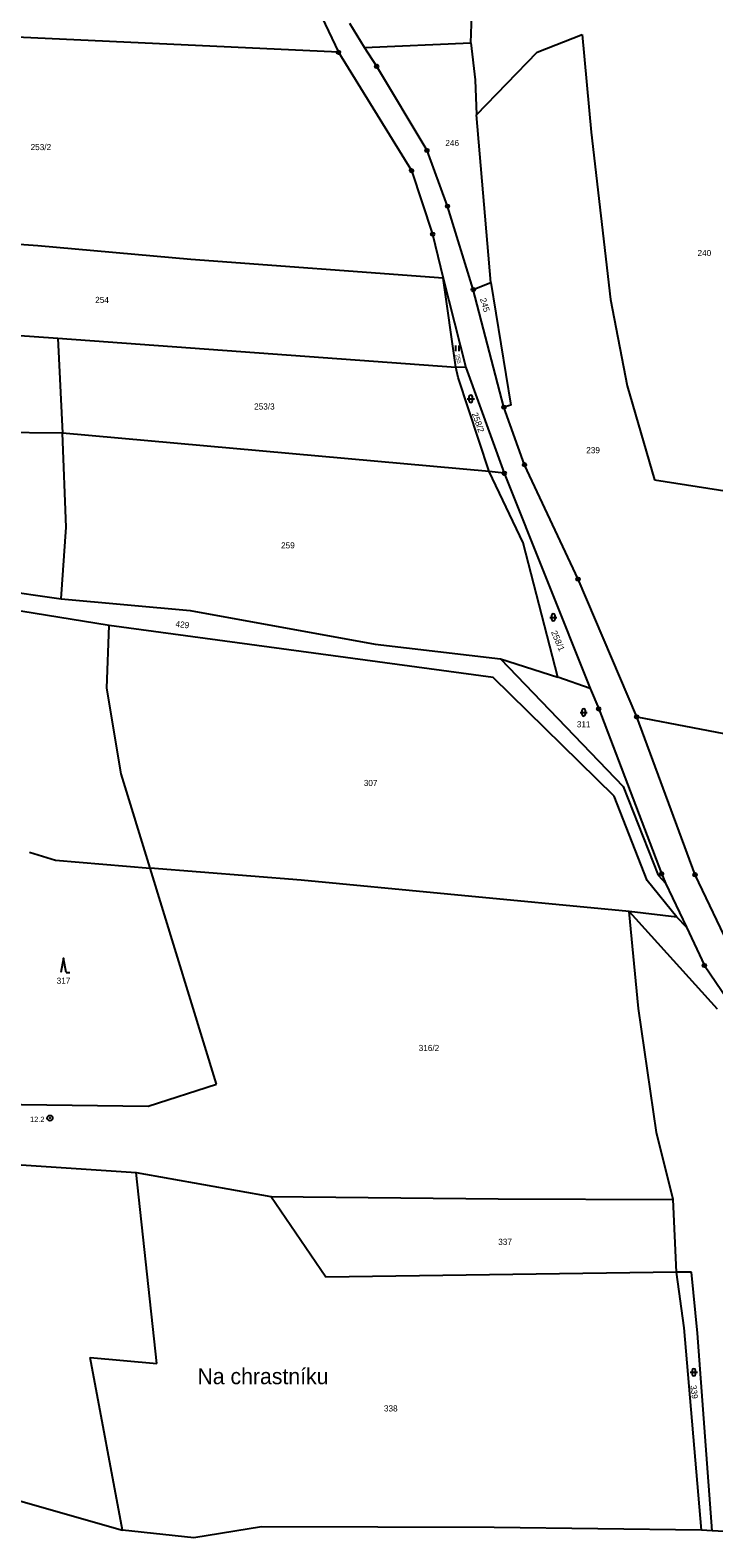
# Model space of a CAD drawing. Extents: x -791548 to -789311, y -1142631 to -1140855.
# Drawn here: x -790850.9 to -790661.5, y -1141946.5 to -1141528.8 of the extents above; entities that cross this region are included whole.
import ezdxf
from ezdxf.enums import TextEntityAlignment as Align

# ---------------------------------------------------------------- set-up
doc = ezdxf.new("R2010")
doc.units = 0
doc.header["$LTSCALE"] = 0.68
for name, color, linetype, lineweight in [('1', 7, 'Continuous', 25), ('3', 7, 'Continuous', 25), ('7', 7, 'Continuous', 13), ('8', 7, 'Continuous', 25)]:
    doc.layers.add(name, color=color, linetype=linetype, lineweight=lineweight)
doc.layers.add('2', color=7, linetype='Continuous')

msp = doc.modelspace()

# ---------------------------------------------------------------- linework, layer by layer
at = {"layer": '1'}
for p, q in [((-790728.86, -1141532.28), (-790728.17, -1141512.41)), ((-790773.86, -1141517.27), (-790765.51, -1141534.95)), ((-790765.51, -1141534.95), (-790858.67, -1141530.56)), ((-790758.27, -1141533.6), (-790762.39, -1141526.97)), ((-790710.48, -1141534.93), (-790698.03, -1141530)), ((-790698.03, -1141530), (-790695.46, -1141557.09)), ((-790758.27, -1141533.6), (-790728.86, -1141532.28)), ((-790754.91, -1141538.86), (-790758.27, -1141533.6)), ((-790728.86, -1141532.28), (-790727.65, -1141542.57)), ((-790765.51, -1141534.95), (-790745.26, -1141567.74)), ((-790740.97, -1141562.16), (-790754.91, -1141538.86)), ((-790727.28, -1141552.3), (-790710.48, -1141534.93)), ((-790727.65, -1141542.57), (-790727.28, -1141552.3)), ((-790723.3, -1141598.76), (-790727.28, -1141552.3)), ((-790695.46, -1141557.09), (-790690.18, -1141603.43)), ((-790735.29, -1141577.58), (-790740.97, -1141562.16)), ((-790745.26, -1141567.74), (-790739.41, -1141585.34)), ((-790728.17, -1141600.68), (-790735.29, -1141577.58)), ((-790848.8, -1141588.58), (-790927.3, -1141582.95)), ((-790806.37, -1141592.33), (-790848.8, -1141588.58)), ((-790739.41, -1141585.34), (-790736.47, -1141597.56)), ((-790736.47, -1141597.56), (-790806.37, -1141592.33)), ((-790732.95, -1141622.2), (-790736.47, -1141597.56)), ((-790736.47, -1141597.56), (-790730.25, -1141622.31)), ((-790728.17, -1141600.68), (-790723.3, -1141598.76)), ((-790719.68, -1141633.27), (-790728.17, -1141600.68)), ((-790723.3, -1141598.76), (-790717.78, -1141632.68)), ((-790690.18, -1141603.43), (-790685.56, -1141627.37)), ((-790918.49, -1141609.09), (-790843.22, -1141614.13)), ((-790843.22, -1141614.13), (-790841.97, -1141640.5)), ((-790843.22, -1141614.13), (-790732.95, -1141622.2)), ((-790732.38, -1141625.05), (-790732.95, -1141622.2)), ((-790730.25, -1141622.31), (-790732.95, -1141622.2)), ((-790730.25, -1141622.31), (-790719.56, -1141651.58)), ((-790723.76, -1141651.14), (-790732.38, -1141625.05)), ((-790685.56, -1141627.37), (-790678, -1141653.37)), ((-790717.78, -1141632.68), (-790719.68, -1141633.27)), ((-790713.97, -1141649.21), (-790719.68, -1141633.27)), ((-790841.97, -1141640.5), (-790867.82, -1141640.21)), ((-790723.76, -1141651.14), (-790841.97, -1141640.5)), ((-790840.96, -1141666.49), (-790841.97, -1141640.5)), ((-790719.56, -1141651.58), (-790723.76, -1141651.14)), ((-790714.34, -1141670.86), (-790723.76, -1141651.14)), ((-790719.56, -1141651.58), (-790695.74, -1141711.19)), ((-790699.13, -1141680.92), (-790713.97, -1141649.21)), ((-790678, -1141653.37), (-790657.29, -1141656.65)), ((-790842.32, -1141686.33), (-790840.96, -1141666.49)), ((-790704.7, -1141708.12), (-790714.34, -1141670.86)), ((-790682.89, -1141719.09), (-790699.13, -1141680.92)), ((-790876.48, -1141681.58), (-790842.32, -1141686.33)), ((-790829.04, -1141693.74), (-790876, -1141686.18)), ((-790842.32, -1141686.33), (-790806.62, -1141689.56)), ((-790806.62, -1141689.56), (-790755.32, -1141698.9)), ((-790829.64, -1141711.14), (-790829.04, -1141693.74)), ((-790722.67, -1141708.15), (-790829.04, -1141693.74)), ((-790755.32, -1141698.9), (-790720.64, -1141702.99)), ((-790720.64, -1141702.99), (-790704.7, -1141708.12)), ((-790720.64, -1141702.99), (-790686.64, -1141738.35)), ((-790689.14, -1141741.02), (-790722.67, -1141708.15)), ((-790695.74, -1141711.19), (-790704.7, -1141708.12)), ((-790825.67, -1141734.82), (-790829.64, -1141711.14)), ((-790695.74, -1141711.19), (-790693.42, -1141716.86)), ((-790693.42, -1141716.86), (-790675.99, -1141762.51)), ((-790666.72, -1141762.82), (-790682.89, -1141719.09)), ((-790682.89, -1141719.09), (-790633.79, -1141728.5)), ((-790817.67, -1141760.96), (-790825.67, -1141734.82)), ((-790686.64, -1141738.35), (-790676.99, -1141762.89)), ((-790679.96, -1141764.42), (-790689.14, -1141741.02)), ((-790851.12, -1141756.58), (-790843.88, -1141758.74)), ((-790843.88, -1141758.74), (-790817.67, -1141760.96)), ((-790775.82, -1141764.34), (-790817.67, -1141760.96)), ((-790799.25, -1141820.82), (-790817.67, -1141760.96)), ((-790735.29, -1141768.23), (-790775.82, -1141764.34)), ((-790671.78, -1141774.56), (-790679.96, -1141764.42)), ((-790676.99, -1141762.89), (-790674.87, -1141765.19)), ((-790675.99, -1141762.51), (-790674.87, -1141765.19)), ((-790656.61, -1141783.86), (-790666.72, -1141762.82)), ((-790684.96, -1141773), (-790735.29, -1141768.23)), ((-790674.87, -1141765.19), (-790669.06, -1141777.3)), ((-790684.96, -1141773), (-790660.62, -1141799.97)), ((-790682.37, -1141799.92), (-790684.96, -1141773)), ((-790671.78, -1141774.56), (-790684.96, -1141773)), ((-790669.06, -1141777.3), (-790671.78, -1141774.56)), ((-790669.06, -1141777.3), (-790664.13, -1141787.97)), ((-790664.13, -1141787.97), (-790656.26, -1141799.55)), ((-790677.43, -1141834.27), (-790682.37, -1141799.92)), ((-790818.25, -1141826.98), (-790799.25, -1141820.82)), ((-790867.97, -1141826.29), (-790818.25, -1141826.98)), ((-790672.75, -1141852.8), (-790677.43, -1141834.27)), ((-790920.31, -1141838.67), (-790821.51, -1141845.34)), ((-790821.51, -1141845.34), (-790784.23, -1141851.93)), ((-790815.8, -1141898.26), (-790821.51, -1141845.34)), ((-790769.02, -1141874.28), (-790784.23, -1141851.93)), ((-790784.23, -1141851.93), (-790721.23, -1141852.63)), ((-790721.23, -1141852.63), (-790672.75, -1141852.8)), ((-790671.88, -1141872.96), (-790672.75, -1141852.8)), ((-790671.88, -1141872.96), (-790769.02, -1141874.28)), ((-790667.69, -1141872.9), (-790671.88, -1141872.96)), ((-790669.75, -1141888.37), (-790671.88, -1141872.96)), ((-790666.08, -1141889.8), (-790667.69, -1141872.9)), ((-790664.9, -1141944.39), (-790669.75, -1141888.37)), ((-790662.02, -1141944.57), (-790666.08, -1141889.8)), ((-790825.32, -1141944.44), (-790834.23, -1141896.56)), ((-790834.23, -1141896.56), (-790815.8, -1141898.26)), ((-790853.52, -1141936.36), (-790825.32, -1141944.44)), ((-790786.82, -1141943.46), (-790805.54, -1141946.54)), ((-790722.41, -1141943.69), (-790786.82, -1141943.46)), ((-790664.9, -1141944.39), (-790722.41, -1141943.69)), ((-790805.54, -1141946.54), (-790825.32, -1141944.44)), ((-790662.02, -1141944.57), (-790664.9, -1141944.39)), ((-790650.61, -1141945.25), (-790662.02, -1141944.57))]:
    msp.add_line(p, q, dxfattribs=at)
at = {"layer": '3'}
for p, q in [((-790733.021, -1141617.72), (-790733.021, -1141616.22)), ((-790732.02, -1141617.72), (-790732.02, -1141616.22)), ((-790729.861, -1141630.951), (-790727.859, -1141630.951)), ((-790729.361, -1141630.451), (-790729.361, -1141631.452)), ((-790728.359, -1141631.452), (-790728.359, -1141630.451)), ((-790706.991, -1141691.511), (-790704.989, -1141691.511)), ((-790706.491, -1141691.011), (-790706.491, -1141692.012)), ((-790705.489, -1141692.012), (-790705.489, -1141691.011)), ((-790698.581, -1141717.841), (-790696.579, -1141717.841)), ((-790698.081, -1141717.341), (-790698.081, -1141718.342)), ((-790697.079, -1141718.342), (-790697.079, -1141717.341)), ((-790840.91, -1141789.9), (-790839.914, -1141789.9)), ((-790668.061, -1141900.671), (-790666.059, -1141900.671)), ((-790667.561, -1141900.171), (-790667.561, -1141901.172)), ((-790666.559, -1141901.172), (-790666.559, -1141900.171))]:
    msp.add_line(p, q, dxfattribs=at)
msp.add_lwpolyline([(-790840.91, -1141789.9), (-790841.66, -1141785.9), (-790842.41, -1141789.9)], dxfattribs=at)
for centre, start, end in [((-790728.86, -1141630.4509), 0, 180), ((-790728.86, -1141631.4509), 180, 359.98789), ((-790705.99, -1141691.0109), 0, 180), ((-790705.99, -1141692.0109), 180, 359.98789), ((-790697.58, -1141717.3409), 0, 180), ((-790697.58, -1141718.3409), 180, 359.98789), ((-790667.06, -1141900.1709), 0, 180), ((-790667.06, -1141901.1709), 180, 359.98789)]:
    msp.add_arc(centre, 0.5, start, end, dxfattribs=at)
at = {"layer": '8'}
for centre, radius in [((-790765.5099, -1141534.95), 0.5), ((-790765.5099, -1141534.95), 0.0303), ((-790754.9099, -1141538.86), 0.5), ((-790754.9099, -1141538.86), 0.0303), ((-790740.9699, -1141562.16), 0.5), ((-790740.9699, -1141562.16), 0.0303), ((-790745.2599, -1141567.74), 0.5), ((-790745.2599, -1141567.74), 0.0303), ((-790735.2899, -1141577.58), 0.5), ((-790735.2899, -1141577.58), 0.0303), ((-790739.4099, -1141585.34), 0.5), ((-790739.4099, -1141585.34), 0.0303), ((-790728.1699, -1141600.68), 0.5), ((-790728.1699, -1141600.68), 0.0303), ((-790719.6799, -1141633.27), 0.5), ((-790719.6799, -1141633.27), 0.0303), ((-790719.5599, -1141651.58), 0.5), ((-790719.5599, -1141651.58), 0.0303), ((-790713.9699, -1141649.21), 0.5), ((-790713.9699, -1141649.21), 0.0303), ((-790699.1299, -1141680.92), 0.5), ((-790699.1299, -1141680.92), 0.0303), ((-790693.4199, -1141716.86), 0.5), ((-790693.4199, -1141716.86), 0.0303), ((-790682.8899, -1141719.09), 0.5), ((-790682.8899, -1141719.09), 0.0303), ((-790675.9899, -1141762.51), 0.5), ((-790675.9899, -1141762.51), 0.0303), ((-790666.7199, -1141762.82), 0.5), ((-790666.7199, -1141762.82), 0.0303), ((-790664.1299, -1141787.97), 0.5), ((-790664.1299, -1141787.97), 0.0303), ((-790845.42, -1141830.2298), 0.75), ((-790845.42, -1141830.2298), 0.03)]:
    msp.add_circle(centre, radius, dxfattribs=at)

# ---------------------------------------------------------------- texts
at = {"layer": '2'}
for s, p in [('246', (-790733.999, -1141560.922)), ('253/2', (-790847.93, -1141562.052)), ('240', (-790664.149, -1141591.412)), ('254', (-790830.989, -1141604.402)), ('253/3', (-790786.02, -1141633.932)), ('239', (-790694.969, -1141646.032)), ('259', (-790779.509, -1141672.402)), ('311', (-790697.579, -1141721.972)), ('307', (-790756.589, -1141738.242)), ('317', (-790841.659, -1141793.032)), ('316/2', (-790740.43, -1141811.662)), ('337', (-790719.349, -1141865.382)), ('338', (-790751.009, -1141911.522))]:
    msp.add_text(s, height=1.7, dxfattribs=at).set_placement(p, align=Align.CENTER)
at = {"layer": '2', "width": 1.05}
for s, rotation, p in [('245', 287, (-790725.7476, -1141605.1905)), ('258/1', 293, (-790705.488, -1141698.3299))]:
    msp.add_text(s, height=1.7, rotation=rotation, dxfattribs=at).set_placement(p, align=Align.CENTER)
at = {"layer": '2'}
for s, height, rotation, p in [('255', 1.14, 282, (-790732.8655, -1141619.999)), ('258/2', 1.7, 290, (-790727.611, -1141637.7863)), ('429', 1.7, 353, (-790808.8336, -1141694.3489)), ('339', 1.7, 277, (-790667.8061, -1141906.2284))]:
    msp.add_text(s, height=height, rotation=rotation, dxfattribs=at).set_placement(p, align=Align.CENTER)
at = {"layer": '7'}
msp.add_text('Na chrastníku', height=4.4, dxfattribs=at).set_placement((-790804.56, -1141903.97))
at = {"layer": '8'}
msp.add_text('12.2', height=1.5, dxfattribs=at).set_placement((-790846.919, -1141831.347), align=Align.RIGHT)

doc.saveas('drawing.dxf')
